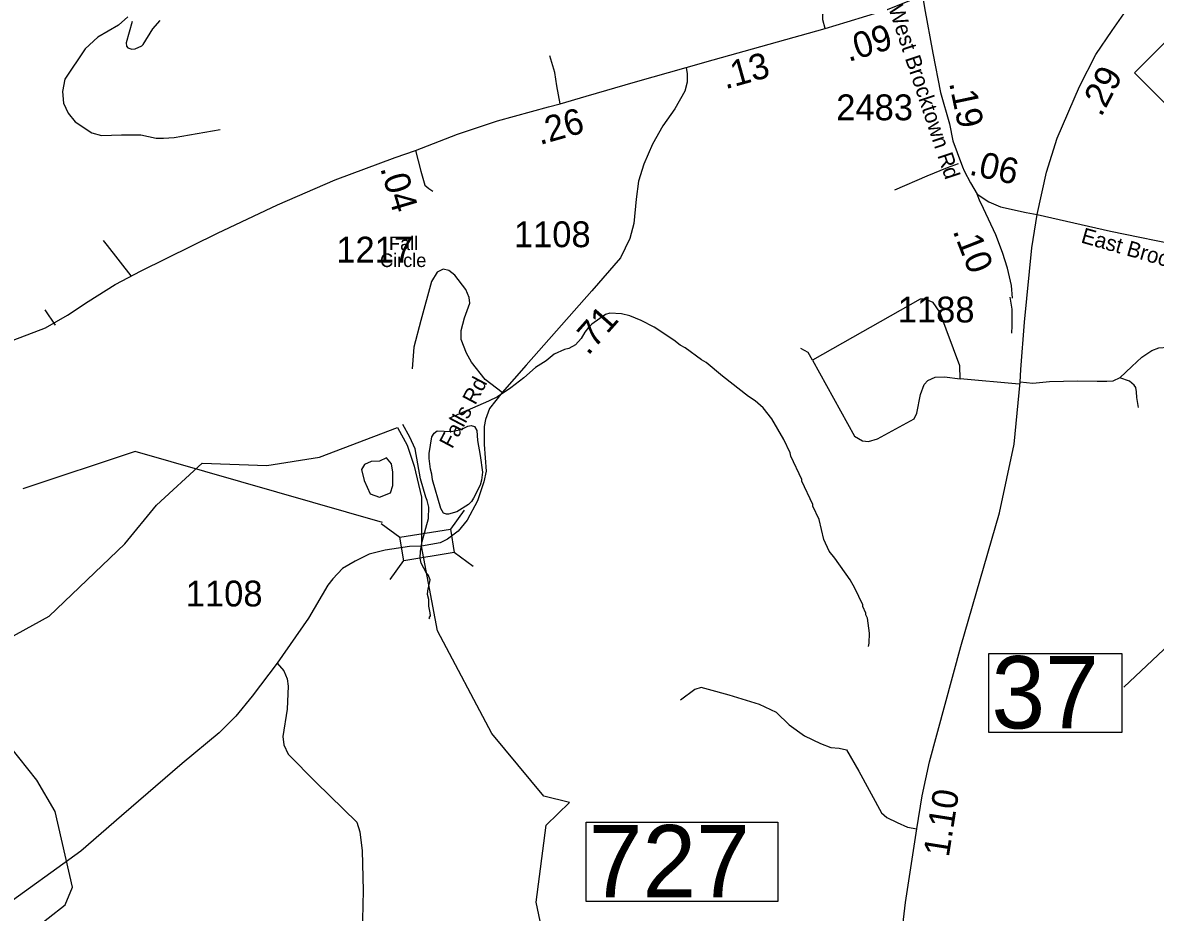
# Model space of a CAD drawing. Extents: x 1248089 to 1457196, y 820910 to 988753.
# Drawn here: x 1350941 to 1356426, y 855863 to 860169 of the extents above; entities that cross this region are included whole.
import ezdxf

# ---------------------------------------------------------------- set-up
doc = ezdxf.new("R2010")
doc.units = 0
for name, color, linetype in [('Exist Hydrographic Creek Single Shore', 7, 'Continuous'), ('Exist Hydrographic Misc Water Feature', 7, 'Continuous'), ('Exist Road Non-System Type 51', 7, 'Continuous'), ('Exist Road Primary NC Attributed', 7, 'Continuous'), ('Exist Road Primary NC Shield CELL', 7, 'Continuous'), ('Exist Road Secondary Structure Standard Bridge CELL', 7, 'Continuous'), ('Exist Road Secondary Structure Standard Bridge Number Label', 7, 'Continuous'), ('Exist Road Secondary Type 51 Attributed', 7, 'Continuous'), ('Exist Road Secondary Type 51 Label', 7, 'Continuous'), ('Prop CMT Slope Fill', 7, 'Continuous'), ('Prop GRAU CAT1 Cell', 7, 'Continuous'), ('Prop Lane Lines', 7, 'Continuous')]:
    doc.layers.add(name, color=color, linetype=linetype)

msp = doc.modelspace()

# ---------------------------------------------------------------- linework, layer by layer
at = {"layer": 'Exist Hydrographic Creek Single Shore'}
for points in [[(1350622.3, 857078.5), (1350647.3, 857110.8), (1350832.4, 857166.3), (1351068.3, 857296.1), (1351435.3, 857646.5), (1351589.3, 857833.8), (1351810.4, 858036.2), (1352122.5, 858025.2), (1352378.8, 858065.9), (1352756, 858208.9), (1352803.5, 858124.8), (1352836.4, 858022.4), (1352872.9, 857872.5), (1352872.2, 857635)], [(1355236.2, 853411.9), (1355127.2, 853537.3), (1355031.4, 853588.9), (1354765.5, 854001.3), (1354629.4, 854273.3), (1354237.4, 854665.2), (1354130.4, 854700.2), (1354081.4, 854750.4), (1354083.4, 854852.1), (1353903.4, 854990.3), (1353765.4, 855167.1), (1353601.4, 855305), (1353497.3, 855582.2), (1353427.9, 855911.2), (1353475.4, 856284.1), (1353588.6, 856393.7), (1353464.7, 856424.9), (1353212.7, 856728.3), (1352949.6, 857225.5), (1352872.2, 857635)]]:
    msp.add_lwpolyline(points, dxfattribs=at)
at = {"layer": 'Exist Hydrographic Misc Water Feature'}
for points in [[(1351470.4, 860174.6), (1351442, 860071.3), (1351443.6, 860055.3), (1351449.5, 860047.1), (1351469.3, 860040.6), (1351485.4, 860042.3), (1351517.7, 860057.4), (1351523.8, 860063.3), (1351571.6, 860140.2), (1351606.4, 860179.3)], [(1355036.7, 857150.1), (1355041.1, 857165.9), (1355042.1, 857213.9), (1355031.7, 857286.2), (1355024.2, 857302.3), (1355024.4, 857310.3), (1355009.1, 857342.7), (1355009.2, 857350.7), (1354971, 857431.6), (1354948, 857472.1), (1354874.4, 857577.8), (1354847.1, 857610.5), (1354820.3, 857667.1), (1354798.5, 857763.6), (1354768, 857828.4), (1354768.1, 857836.4), (1354714.7, 857949.6), (1354714.9, 857957.6), (1354661.5, 858070.8), (1354657.8, 858086.9), (1354627.3, 858151.7), (1354569.6, 858251), (1354526.7, 858304), (1354487.5, 858339), (1354456, 858359.7), (1354330.2, 858458.7), (1354251.6, 858524.6), (1354227.9, 858537.1), (1354149.2, 858595), (1354125.5, 858607.6), (1354094, 858632.3), (1353999.4, 858694.6), (1353936.1, 858728), (1353880.7, 858749.4), (1353840.9, 858760.3), (1353784.9, 858763.7), (1353762.8, 858756.2), (1353697.7, 858709.7), (1353681.4, 858694.1), (1353662.8, 858670.6), (1353646.1, 858641), (1353617.4, 858609.7), (1353585, 858592.4), (1353564.9, 858586.9), (1353514.4, 858564.1), (1353475.6, 858533), (1353424.8, 858500.3), (1353367.7, 858449.6), (1353304.6, 858401.1), (1353239.7, 858358.7), (1353197.1, 858337.7), (1353005.3, 858253.2)], [(1352912.2, 857283.2), (1352909.3, 857288.7), (1352915.5, 857298.6), (1352914.3, 857311.8), (1352908.5, 857344.7), (1352907.3, 857376.7), (1352901.9, 857400.8), (1352902.3, 857418.8), (1352913.4, 857472.6), (1352904, 857496.8), (1352896.2, 857505), (1352871.3, 857553.5), (1352865.9, 857577.7), (1352866.6, 857611.7), (1352875.6, 857657.5), (1352906.2, 857768.7), (1352907.4, 857824.7), (1352900.2, 857856.8), (1352892.5, 857873), (1352866.6, 857961.6), (1352841.8, 858106.2), (1352815.1, 858162.8), (1352781.5, 858224.7)], [(1352933.4, 858182.7), (1352947.7, 858193.1), (1353015.5, 858189.5), (1353063.8, 858200.3), (1353096.2, 858215.5), (1353112.3, 858219.2), (1353128.2, 858214.8), (1353139.7, 858194.5), (1353142.7, 858146.4), (1353157, 858074.1), (1353167.2, 857993.9), (1353162.3, 857954), (1353155.7, 857930.2), (1353124.3, 857866.9), (1353114, 857851.2), (1353099.6, 857837.5), (1353042.8, 857800.9), (1353002.5, 857789.9), (1352993.1, 857790), (1352978.6, 857794.4), (1352965.1, 857816.7), (1352926.2, 857955.6), (1352922.9, 857983.7), (1352915.5, 858007.9), (1352908.6, 858060.1), (1352909.1, 858084), (1352923, 858163.7), (1352933.4, 858182.7)], [(1352628.8, 858045.7), (1352596.6, 858030.3), (1352582.1, 858006.6), (1352595, 857952.3), (1352623.7, 857887.7), (1352669.5, 857872.7), (1352721.9, 857893.7), (1352732.6, 857929.5), (1352733.9, 857993.5), (1352726.8, 858033.7), (1352703.3, 858062.2), (1352668.9, 858046.9), (1352628.8, 858045.7)], [(1351884.4, 850047.6), (1351916.4, 850723.3), (1351813.4, 850991.2), (1351701.4, 851193.7), (1351220.4, 851695.8), (1351092.4, 851957.7), (1351096.4, 852515.7), (1350913.4, 853277.7), (1350915.1, 853464), (1351081.4, 853701.1), (1351305.3, 854422.1), (1351293.3, 854629.2), (1351034.4, 854985.6), (1350962.4, 855128.2), (1350783.4, 855309.1), (1350727.4, 855418.5), (1350737.3, 855526.7), (1350815.4, 855640.1), (1351146.3, 855899.3), (1351181.4, 855984), (1351097.3, 856350), (1351009.3, 856502.8), (1350790.3, 856776.4), (1350622.3, 857078.5)]]:
    msp.add_lwpolyline(points, dxfattribs=at)
at = {"layer": 'Exist Road Non-System Type 51'}
msp.add_line((1355766.3, 858419.6), (1355481, 858445), dxfattribs=at)
for points in [[(1351449.4, 860196.9), (1351405.3, 860157.6), (1351304.8, 860098.8), (1351243.6, 860042.4), (1351145.6, 859895.3), (1351133.3, 859836.4), (1351138.2, 859780), (1351160.3, 859731), (1351194.6, 859689.3), (1351275.4, 859635.4), (1351322, 859623.1), (1351420, 859625.6), (1351513.1, 859625.6), (1351586.6, 859610.8), (1351623.4, 859610.8), (1351674.8, 859613.3), (1351897.8, 859652.5)], [(1353543.8, 859776.8), (1353527.5, 859863.7), (1353518.4, 859928.8), (1353493.1, 860008.4)], [(1355164.2, 859359.5), (1355321.5, 859428.3), (1355419.1, 859468.1), (1355473.4, 859488)], [(1351466.5, 858943.9), (1351351.4, 859091), (1351331.8, 859115.5)], [(1353262.5, 858378.9), (1353181.1, 858442.3), (1353114.2, 858525.5), (1353090.7, 858568.9), (1353063.6, 858635.9), (1353063.6, 858679.3), (1353079.8, 858740.8), (1353107, 858811.4), (1353103.4, 858839.7), (1353087.1, 858877.7), (1353032.9, 858946.5), (1353004, 858970), (1352976.8, 858975.4), (1352947.9, 858961), (1352920.8, 858915.7), (1352868.4, 858727.5), (1352835.8, 858599.1), (1352826.8, 858494.1)], [(1355481, 858445), (1355479, 858507.6), (1355383.3, 858767.7), (1355350, 858814.7), (1355310.9, 858830.3), (1355287.5, 858830.3), (1354765.6, 858535)], [(1355722.1, 858839.8), (1355730.9, 858782.5), (1355730.9, 858701.1), (1355729.1, 858666.7)], [(1351099.6, 858705.4), (1351049.5, 858778.8)], [(1354765.6, 858535), (1354744.1, 858572.1), (1354708.9, 858591.7)], [(1356253.6, 858450), (1356313.2, 858504.3), (1356360.2, 858549.5), (1356409, 858582.1), (1356443.4, 858594.7), (1356486.8, 858598.3), (1356520.7, 858594.6), (1356562.2, 858571), (1356634.6, 858531.2), (1356667.1, 858511.3), (1356703.3, 858495.1), (1356735.8, 858495.1), (1356768.4, 858500.5), (1356844.3, 858520.4)], [(1354765.6, 858535), (1354968.9, 858167.2), (1355008, 858145.7), (1355037.3, 858141.8), (1355080.3, 858155.5), (1355258.2, 858251.4), (1355271.8, 858278.7), (1355289.4, 858368.7), (1355307, 858417.6), (1355324.6, 858437.2), (1355359.8, 858452.8), (1355404.8, 858454.8), (1355481, 858445)], [(1356253.6, 858450), (1356221, 858433.7), (1356192.1, 858431.9), (1356145.1, 858431.9), (1356049.2, 858433.7), (1355913.6, 858430.1), (1355832.3, 858422.8), (1355771, 858428.9)], [(1356344, 858307), (1356336.7, 858354.1), (1356334.9, 858383), (1356331.3, 858402.9), (1356324.1, 858413.8), (1356300.6, 858433.7), (1356253.6, 858450)], [(1354591.1, 856829.5), (1354509.8, 856869.4), (1354361.5, 856914.6), (1354262.1, 856941.7), (1354225.9, 856950.8), (1354195.2, 856941.7), (1354126.5, 856889.3)], [(1354591.1, 856829.5), (1354652.6, 856769.8), (1354726.7, 856717.4), (1354804.5, 856679.4), (1354855.1, 856661.3), (1354894.9, 856657.7), (1354931, 856648.6), (1354990.4, 856546.4), (1355100.7, 856343.7), (1355126, 856322), (1355176.6, 856296.7), (1355225.4, 856275), (1355271.4, 856266.1)]]:
    msp.add_lwpolyline(points, dxfattribs=at)
at = {"layer": 'Exist Road Primary NC Attributed'}
for points in [[(1355854.4, 859240.5), (1355898.6, 859445.5), (1355950.1, 859610.3), (1356059.8, 859860.9), (1356138.7, 860015.3), (1356217.6, 860132), (1356363.6, 860343.5), (1356530.1, 860576.4)], [(1354827.3, 860141.6), (1354933, 860173.1), (1355123.6, 860231.6), (1355298.7, 860301.7)], [(1354153.8, 859952.6), (1354284.5, 859989.3), (1354827.3, 860141.6)], [(1352843, 859549.9), (1353046.8, 859629.4), (1353240.6, 859694.1), (1353486.6, 859761.2), (1353543.8, 859776.8), (1353670.4, 859813.4), (1353908.3, 859882.2), (1354153.8, 859952.6)], [(1349857.1, 858249.7), (1350081.3, 858384.5), (1350200.6, 858451.6), (1350272.6, 858483.9), (1350342.2, 858511.3), (1350449, 858546.1), (1350514.1, 858561.2), (1350618.2, 858579.5), (1350774.4, 858607.8), (1350894.9, 858632.5), (1351051.1, 858691.9), (1351158.5, 858752.8), (1351258.1, 858819.5), (1351388.7, 858901.8), (1351513.8, 858967.6), (1351884.1, 859150.7), (1352174.5, 859287.8), (1352454.4, 859408), (1352743.9, 859516.8), (1352843, 859549.9)], [(1355494.3, 853553.2), (1355397.4, 853824.6), (1355281.1, 854161), (1355214.3, 854445), (1355174.5, 854803.7), (1355158.5, 855239), (1355172.9, 855533.9), (1355192, 855706), (1355215.6, 855910.6), (1355271.4, 856266.1), (1355296.9, 856427.1), (1355331.8, 856591.7), (1355484.5, 857150.1), (1355672.3, 857796), (1355742.4, 858129.2), (1355771, 858428.9), (1355774.1, 858489.6), (1355793.2, 858719.2), (1355828.3, 859079.4), (1355854.4, 859240.5)]]:
    msp.add_lwpolyline(points, dxfattribs=at)
at = {"layer": 'Exist Road Primary NC Shield CELL'}
msp.add_lwpolyline([(1356325.8, 859925.8), (1356658.8, 860258.8), (1356991.8, 859925.8), (1356658.8, 859592.8)], close=True, dxfattribs=at)
at = {"layer": 'Exist Road Secondary Structure Standard Bridge CELL'}
for p, q in [((1353078.9, 857809.7), (1353012.4, 857718)), ((1352768, 857677), (1352676.4, 857743.4)), ((1353122.3, 857537.2), (1353030.7, 857603.7)), ((1352785.8, 857565.2), (1352719.4, 857473.6))]:
    msp.add_line(p, q, dxfattribs=at)
msp.add_lwpolyline([(1353030.7, 857603.7), (1352785.9, 857564.7), (1352767.7, 857679), (1353012.4, 857718)], close=True, dxfattribs=at)
at = {"layer": 'Exist Road Secondary Structure Standard Bridge Number Label'}
msp.add_line((1357596.1, 858199.8), (1356273.2, 856953.3), dxfattribs=at)
msp.add_lwpolyline([(1352683.7, 857749.2), (1351486.1, 858093.9), (1350941.7, 857912.5)], dxfattribs=at)
for points in [[(1355619.8, 857115.4), (1356263.9, 857115.4), (1356263.9, 856733.1), (1355619.8, 856733.1)], [(1353669.4, 856299.6), (1354598.3, 856299.6), (1354598.3, 855915.5), (1353669.4, 855915.5)]]:
    msp.add_lwpolyline(points, close=True, dxfattribs=at)
at = {"layer": 'Exist Road Secondary Type 51 Attributed'}
for points in [[(1354827.3, 860141.6), (1354816.7, 860183.5), (1354816.7, 860209.3), (1354827, 860236.7), (1354892.1, 860301.9), (1354972.7, 860396.3)], [(1355298.7, 860301.7), (1355308.3, 860241.7), (1355348.1, 860021.8), (1355386.3, 859830.9), (1355428.8, 859678.9), (1355446, 859596.6), (1355466.5, 859541.6), (1355492.8, 859471.1), (1355500.5, 859451.3), (1355531.7, 859394), (1355563.7, 859338.5)], [(1354153.8, 859952.6), (1354159.6, 859921.7), (1354159.6, 859881.9), (1354147.2, 859837.2), (1354099.9, 859752.6), (1354040.3, 859670.6), (1353990.6, 859581.1), (1353948.4, 859484.1), (1353923.5, 859402), (1353911.1, 859315), (1353901.2, 859197.1), (1353881.4, 859125), (1353836.6, 859030.5), (1353697.5, 858871.4), (1353379.5, 858510.8), (1353262.5, 858378.9), (1353201, 858301.1), (1353182.2, 858248.8), (1353175.8, 858215), (1353175.8, 858127.3), (1353184.9, 857997.9), (1353174, 857946.8), (1353142.9, 857855.4), (1353093.6, 857760.3), (1353049.8, 857707.3), (1352998.6, 857668.9), (1352962.1, 857650.6), (1352872.2, 857635)], [(1352843, 859549.9), (1352868.2, 859450.6), (1352888, 859383.5), (1352907.9, 859366.1), (1352927.8, 859353.6)], [(1355734, 858836.3), (1355728.9, 858896.4), (1355710, 858980.5), (1355686, 859056), (1355653.4, 859141.8), (1355593.4, 859270.5), (1355574.6, 859309.9), (1355563.7, 859338.5)], [(1355563.7, 859338.5), (1355620.2, 859302.7), (1355676.7, 859277.9), (1355800.7, 859250.3), (1355854.4, 859240.5)], [(1355854.4, 859240.5), (1356208.9, 859159.9), (1356572.6, 859085.4), (1356823.4, 859027.5), (1356897.8, 858999.9), (1356936.4, 858966.8), (1356994.2, 858900.6), (1357074.1, 858771), (1357107.2, 858718.6), (1357217.6, 858616.2), (1357365.9, 858502.5), (1357436.5, 858441.3), (1357490.2, 858389.6), (1357550.3, 858329.5), (1357606.2, 858285.2), (1357650.5, 858268.3)], [(1352872.2, 857635), (1352814.6, 857634), (1352696.8, 857615.8), (1352619.2, 857596.6), (1352550.7, 857562.8), (1352489.7, 857527), (1352442.7, 857476.3), (1352418.9, 857446.3), (1352324.5, 857287.1), (1352172.9, 857068.3)], [(1352172.9, 857068.3), (1352051.8, 856909), (1351972.6, 856812.7), (1351891.5, 856731.6), (1351712.3, 856582.5), (1351420, 856329.6), (1351222.4, 856158.7), (1350833.9, 855877.5)], [(1352172.9, 857068.3), (1352205.7, 857032.3), (1352222.4, 856993.3), (1352226.6, 856957.2), (1352221, 856845.9), (1352200.1, 856713.7), (1352205.7, 856673.3), (1352226.6, 856628.8), (1352361.4, 856491.1), (1352558.3, 856298.7), (1352573.6, 856252.7), (1352584.7, 856159.5), (1352590.3, 855968.9), (1352584.8, 855755.7)]]:
    msp.add_lwpolyline(points, dxfattribs=at)

# ---------------------------------------------------------------- texts
at = {"layer": 'Exist Road Secondary Structure Standard Bridge Number Label'}
for s, p in [('37', (1355632.3, 856752.8)), ('727', (1353681.9, 855935.2))]:
    msp.add_text(s, height=350, dxfattribs=at).set_placement(p)
at = {"layer": 'Exist Road Secondary Type 51 Label'}
for s, rotation, p in [('West Brocktown Rd', 288.4386, (1355132, 860240.6)), ('East Brocktown Rd', 344.126, (1356062.2, 859106)), ('Falls Rd', 62.1476, (1353020.8, 858103.2))]:
    msp.add_text(s, height=75, rotation=rotation, dxfattribs=at).set_placement(p)
for s, p in [('Fall', (1352714.8, 859068.4)), ('Circle', (1352671.5, 858986.4))]:
    msp.add_text(s, height=65.62, dxfattribs=at).set_placement(p)
at = {"layer": 'Prop CMT Slope Fill'}
for s, rotation, p in [('.09', 17.0598, (1354940.1, 859978.7)), ('.13', 15.6736, (1354343.7, 859846.3)), ('.29', 62.4226, (1356163.8, 859709.1)), ('.26', 15.8549, (1353445.2, 859576.5)), ('1.10', 81.0054, (1355425.7, 856126.5))]:
    msp.add_text(s, height=125, rotation=rotation, dxfattribs=at).set_placement(p)
at = {"layer": 'Prop GRAU CAT1 Cell'}
for s, rotation, p in [('.19', 281.8923, (1355426.7, 859877.9)), ('.06', 347.4617, (1355520.1, 859434.7)), ('.04', 286.4919, (1352671.2, 859464.9)), ('.10', 291.4613, (1355443.8, 859161.3)), ('.71', 48.4907, (1353678.8, 858554.3))]:
    msp.add_text(s, height=125, rotation=rotation, dxfattribs=at).set_placement(p)
at = {"layer": 'Prop Lane Lines'}
for s, p in [('2483', (1354880.8, 859696.9)), ('1108', (1353319.6, 859082.4)), ('1217', (1352459.5, 859008)), ('1188', (1355178.7, 858718)), ('1108', (1351730.5, 857343.3))]:
    msp.add_text(s, height=125, dxfattribs=at).set_placement(p)

doc.saveas('drawing.dxf')
